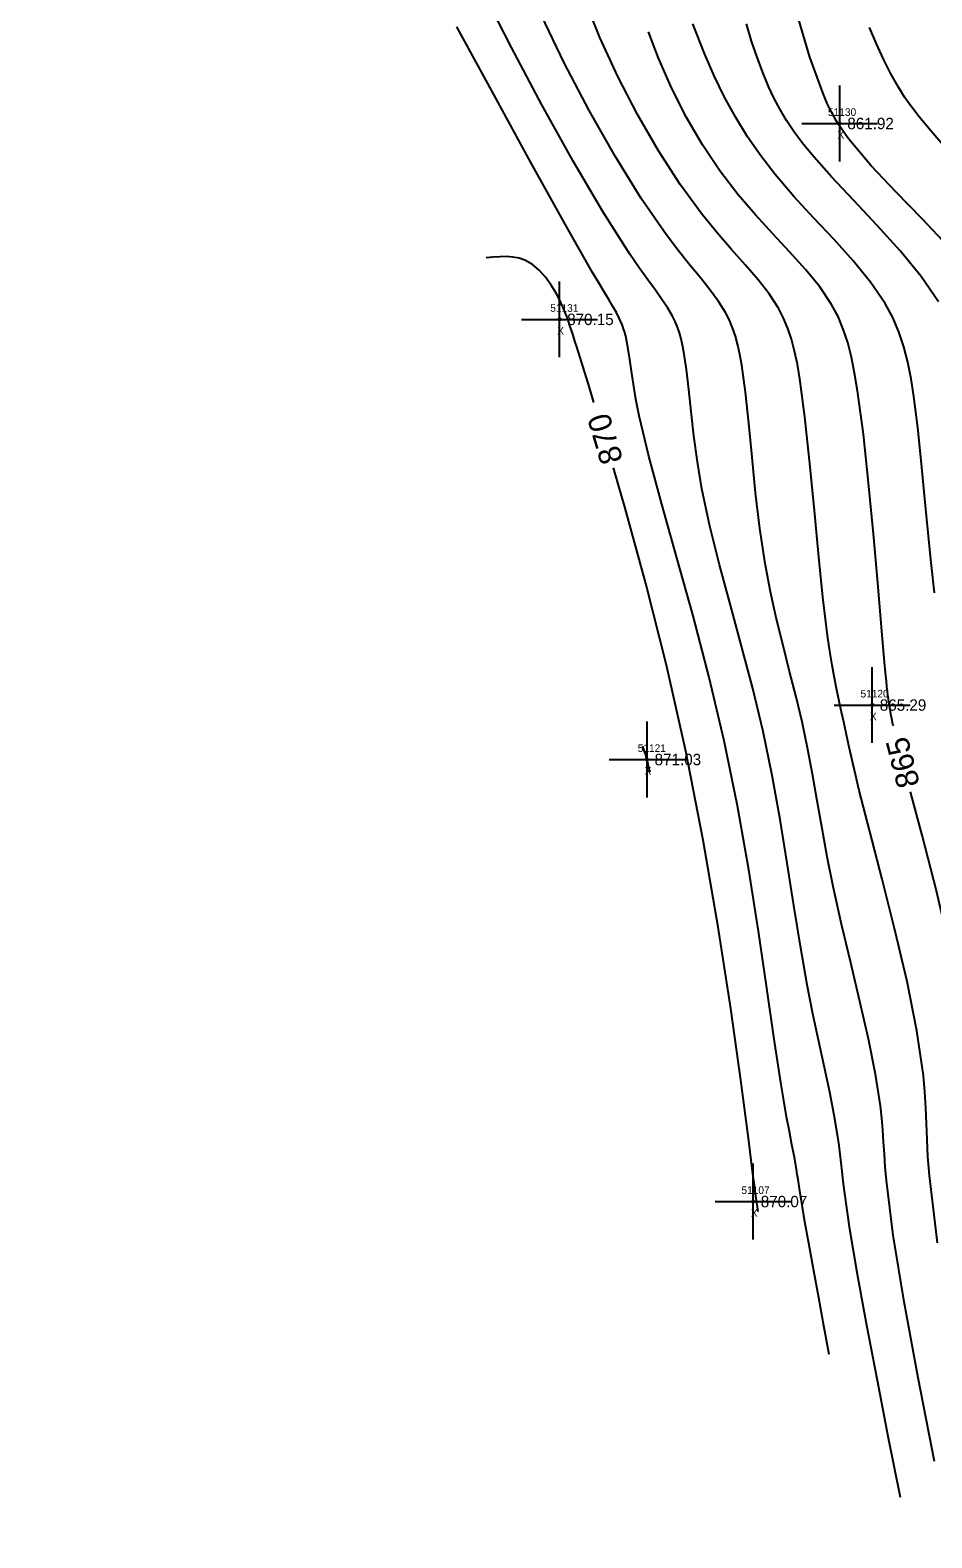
# Model space of a CAD drawing. Extents: x 1378535 to 1380697, y 997729 to 1000024.
# Drawn here: x 1380345.6 to 1380464.6, y 997856.9 to 998055.6 of the extents above; entities that cross this region are included whole.
import ezdxf

# ---------------------------------------------------------------- set-up
doc = ezdxf.new("R2010")
doc.units = 0
for name, color, linetype in [('RD_DTM_BkLn1', 7, 'Continuous'), ('RD_DTM_Major1', 7, 'Continuous'), ('RD_DTM_Major1_Lbl', 7, 'Continuous'), ('RD_DTM_Minor1', 7, 'Continuous'), ('RD_EX_Misc', 7, 'Continuous'), ('RD_EX_Misc_txCode', 7, 'Continuous'), ('RD_EX_Road', 7, 'Continuous'), ('RD_EX_TX_Misc_ELEV', 7, 'Continuous'), ('RD_SMD_Locator', 7, 'Continuous')]:
    doc.layers.add(name, color=color, linetype=linetype)

msp = doc.modelspace()

# ---------------------------------------------------------------- linework, layer by layer
at = {"layer": 'RD_DTM_BkLn1'}
msp.add_spline([(1380561.34, 997899.22), (1380543.7, 997960.78), (1380525.01, 998016.6), (1380501.32, 998075.31), (1380476.75, 998129.12), (1380448.82, 998181.2), (1380418.35, 998233.12), (1380383.22, 998285.15), (1380349.47, 998331.42), (1380310.82, 998378.03), (1380271.62, 998420.47), (1380231.53, 998459.85)], degree=3, dxfattribs=at)
at = {"layer": 'RD_DTM_Major1'}
for points in [[(1380459.47, 997963.94), (1380459.42, 997964.16), (1380459.28, 997964.83), (1380459.15, 997965.44), (1380459.08, 997965.86), (1380459, 997966.26), (1380458.94, 997966.66), (1380458.88, 997967.06), (1380458.82, 997967.47), (1380458.76, 997967.9), (1380458.69, 997968.48), (1380458.62, 997969.11), (1380458.55, 997969.79), (1380458.47, 997970.54), (1380458.39, 997971.37), (1380458.31, 997972.29), (1380457.91, 997976.94), (1380457.42, 997982.75), (1380456.85, 997989.24), (1380456.21, 997995.94), (1380455.51, 998002.38), (1380454.75, 998008.08), (1380454.36, 998010.42), (1380453.94, 998012.52), (1380453.45, 998014.43), (1380452.87, 998016.2), (1380452.17, 998017.85), (1380451.32, 998019.44), (1380449.75, 998021.76), (1380447.88, 998024.06), (1380445.79, 998026.39), (1380443.56, 998028.78), (1380441.27, 998031.27), (1380439.01, 998033.91), (1380436.59, 998037.08), (1380434.31, 998040.48), (1380432.19, 998044.08), (1380430.24, 998047.9), (1380428.48, 998051.91), (1380427.18, 998055.37)], [(1380419.98, 998006.55), (1380419.39, 998008.5), (1380417.72, 998013.86), (1380417.51, 998014.5), (1380417.32, 998015.1), (1380417.15, 998015.66), (1380416.98, 998016.17), (1380416.81, 998016.66), (1380416.65, 998017.12), (1380416.59, 998017.32), (1380416.52, 998017.51), (1380416.45, 998017.7), (1380416.38, 998017.88), (1380416.31, 998018.07), (1380416.24, 998018.25), (1380416.13, 998018.52), (1380416.02, 998018.78), (1380415.91, 998019.04), (1380415.79, 998019.3), (1380415.67, 998019.56), (1380415.55, 998019.83), (1380414.98, 998020.93), (1380414.33, 998022.02), (1380413.6, 998023.05), (1380412.77, 998023.97), (1380411.87, 998024.73), (1380410.88, 998025.29), (1380410.09, 998025.55), (1380409.27, 998025.7), (1380408.42, 998025.76), (1380407.54, 998025.74), (1380406.65, 998025.69), (1380405.75, 998025.61)], [(1380441.64, 997899.9), (1380441.54, 997900.54), (1380441.46, 997901.04), (1380441.37, 997901.64), (1380441.36, 997901.75), (1380441.34, 997901.86), (1380441.32, 997901.97), (1380441.28, 997902.27), (1380441.24, 997902.59), (1380441.2, 997902.93), (1380441.15, 997903.31), (1380441.09, 997903.72), (1380441.04, 997904.16), (1380440.35, 997909.56), (1380439.35, 997917.23), (1380438.02, 997926.67), (1380436.37, 997937.37), (1380434.39, 997948.84), (1380432.09, 997960.57), (1380429.53, 997971.91), (1380426.81, 997982.69), (1380424.11, 997992.59), (1380422.56, 997997.93)], [(1380478.43, 997856.9), (1380477.24, 997862.31), (1380475.33, 997871.26), (1380473.42, 997880.79), (1380471.7, 997890.27), (1380470.37, 997899.12), (1380469.61, 997906.72), (1380469.51, 997909.33), (1380469.48, 997911.74), (1380469.48, 997914.03), (1380469.47, 997916.3), (1380469.4, 997918.65), (1380469.22, 997921.17), (1380468.33, 997927.57), (1380466.89, 997934.75), (1380465.14, 997942.19), (1380463.3, 997949.35), (1380461.73, 997955.23)]]:
    msp.add_lwpolyline(points, dxfattribs=at)
at = {"layer": 'RD_DTM_Minor1'}
for points in [[(1380460.41, 997862.23), (1380458.85, 997870.03), (1380457.36, 997877.64), (1380455.97, 997884.89), (1380454.74, 997891.59), (1380453.74, 997897.56), (1380453.01, 997902.61), (1380452.85, 997903.92), (1380452.71, 997905.16), (1380452.58, 997906.34), (1380452.45, 997907.48), (1380452.31, 997908.62), (1380452.16, 997909.76), (1380451.68, 997912.61), (1380451.08, 997915.65), (1380450.38, 997918.88), (1380449.63, 997922.3), (1380448.85, 997925.94), (1380448.09, 997929.79), (1380447.2, 997934.88), (1380446.34, 997940.26), (1380445.47, 997945.84), (1380444.53, 997951.57), (1380443.48, 997957.37), (1380442.28, 997963.17), (1380440.93, 997968.83), (1380439.46, 997974.4), (1380437.97, 997979.84), (1380436.55, 997985.14), (1380435.27, 997990.25), (1380434.22, 997995.14), (1380433.62, 997998.73), (1380433.15, 998002.14), (1380432.79, 998005.33), (1380432.48, 998008.25), (1380432.18, 998010.88), (1380431.84, 998013.17), (1380431.67, 998014.08), (1380431.48, 998014.92), (1380431.25, 998015.71), (1380430.99, 998016.46), (1380430.69, 998017.19), (1380430.34, 998017.91), (1380429.71, 998018.99), (1380428.95, 998020.12), (1380428.08, 998021.34), (1380427.08, 998022.71), (1380425.95, 998024.28), (1380424.71, 998026.08), (1380421.2, 998031.61), (1380417.25, 998038.34), (1380413.12, 998045.76), (1380409.08, 998053.34), (1380405.41, 998060.57)], [(1380465.29, 997895.79), (1380464.22, 997904.67), (1380464.04, 997907.14), (1380463.93, 997909.4), (1380463.85, 997911.52), (1380463.76, 997913.58), (1380463.64, 997915.66), (1380463.44, 997917.85), (1380462.58, 997923.7), (1380461.27, 997930.22), (1380459.68, 997937.02), (1380457.99, 997943.73), (1380456.37, 997949.99), (1380454.98, 997955.41), (1380454.47, 997957.51), (1380454.03, 997959.4), (1380453.64, 997961.13), (1380453.29, 997962.73), (1380452.96, 997964.24), (1380452.65, 997965.71), (1380452.33, 997967.16), (1380452.02, 997968.64), (1380451.7, 997970.21), (1380451.38, 997971.91), (1380451.07, 997973.76), (1380450.77, 997975.83), (1380450.17, 997980.87), (1380449.59, 997986.64), (1380449.02, 997992.77), (1380448.43, 997998.89), (1380447.81, 998004.65), (1380447.13, 998009.67), (1380446.81, 998011.57), (1380446.45, 998013.3), (1380446.04, 998014.87), (1380445.56, 998016.31), (1380444.99, 998017.67), (1380444.31, 998018.97), (1380443.08, 998020.84), (1380441.62, 998022.72), (1380439.96, 998024.64), (1380438.14, 998026.68), (1380436.22, 998028.88), (1380434.24, 998031.31), (1380431.34, 998035.28), (1380428.47, 998039.71), (1380425.7, 998044.5), (1380423.11, 998049.51), (1380420.76, 998054.63), (1380418.72, 998059.75)], [(1380464.91, 997866.98), (1380462.74, 997877.98), (1380460.89, 997888.02), (1380459.46, 997896.8), (1380458.56, 997903.99), (1380458.4, 997905.79), (1380458.29, 997907.47), (1380458.18, 997909.07), (1380458.08, 997910.63), (1380457.95, 997912.2), (1380457.78, 997913.82), (1380457.12, 997918.03), (1380456.19, 997922.67), (1380455.07, 997927.6), (1380453.86, 997932.67), (1380452.65, 997937.77), (1380451.54, 997942.75), (1380450.76, 997946.64), (1380450.07, 997950.39), (1380449.42, 997954.02), (1380448.79, 997957.56), (1380448.14, 997961.02), (1380447.42, 997964.43), (1380446.63, 997967.76), (1380445.78, 997971.1), (1380444.92, 997974.49), (1380444.06, 997977.96), (1380443.26, 997981.56), (1380442.55, 997985.32), (1380441.86, 997989.93), (1380441.3, 997994.65), (1380440.83, 997999.33), (1380440.4, 998003.8), (1380439.96, 998007.9), (1380439.47, 998011.47), (1380439.23, 998012.85), (1380438.96, 998014.11), (1380438.64, 998015.28), (1380438.27, 998016.37), (1380437.84, 998017.4), (1380437.33, 998018.4), (1380436.41, 998019.86), (1380435.32, 998021.34), (1380434.06, 998022.91), (1380432.66, 998024.61), (1380431.12, 998026.52), (1380429.48, 998028.68), (1380426.21, 998033.44), (1380422.78, 998038.99), (1380419.33, 998045.04), (1380416.04, 998051.32), (1380413.06, 998057.52)], [(1380466.71, 998027.09), (1380463.26, 998030.73), (1380459.78, 998034.3), (1380456.54, 998037.74), (1380453.8, 998040.96), (1380453.47, 998041.41), (1380453.14, 998041.85), (1380452.83, 998042.29), (1380452.54, 998042.73), (1380452.25, 998043.17), (1380451.98, 998043.62), (1380451.66, 998044.18), (1380451.35, 998044.76), (1380451.05, 998045.35), (1380450.76, 998045.96), (1380450.47, 998046.59), (1380450.19, 998047.25), (1380448.47, 998052.04), (1380446.78, 998057.7)], [(1380451.02, 997881.07), (1380450.31, 997884.84), (1380449.62, 997888.54), (1380448.96, 997892.11), (1380448.35, 997895.47), (1380447.81, 997898.55), (1380447.35, 997901.3), (1380447.23, 997902.05), (1380446.91, 997904.13), (1380446.8, 997904.79), (1380446.69, 997905.45), (1380446.41, 997907.05), (1380446.1, 997908.71), (1380445.76, 997910.47), (1380445.39, 997912.4), (1380445.01, 997914.53), (1380444.61, 997916.91), (1380443.74, 997922.62), (1380442.78, 997929.34), (1380441.68, 997936.85), (1380440.4, 997944.94), (1380438.91, 997953.38), (1380437.15, 997961.95), (1380435.17, 997970.31), (1380433.05, 997978.41), (1380430.92, 997986.08), (1380428.93, 997993.15), (1380427.23, 997999.45), (1380425.95, 998004.79), (1380425.52, 998006.98), (1380425.19, 998008.93), (1380424.93, 998010.66), (1380424.72, 998012.2), (1380424.51, 998013.57), (1380424.28, 998014.79), (1380424.16, 998015.28), (1380424.03, 998015.76), (1380423.89, 998016.23), (1380423.72, 998016.69), (1380423.53, 998017.16), (1380423.31, 998017.64), (1380422.93, 998018.39), (1380422.47, 998019.2), (1380421.94, 998020.11), (1380421.32, 998021.14), (1380420.61, 998022.32), (1380419.8, 998023.68), (1380416.16, 998030.06), (1380411.67, 998038.17), (1380406.77, 998047.13), (1380401.89, 998056.06)], [(1380464.89, 997981.44), (1380464.44, 997985.45), (1380464.01, 997989.8), (1380463.59, 997994.33), (1380463.16, 997998.87), (1380462.69, 998003.26), (1380462.17, 998007.34), (1380461.81, 998009.66), (1380461.38, 998011.83), (1380460.86, 998013.88), (1380460.21, 998015.83), (1380459.39, 998017.73), (1380458.38, 998019.6), (1380456.47, 998022.39), (1380454.18, 998025.19), (1380451.65, 998028), (1380448.99, 998030.84), (1380446.36, 998033.7), (1380443.87, 998036.57), (1380441.97, 998039.03), (1380440.24, 998041.53), (1380438.67, 998044.1), (1380437.21, 998046.77), (1380435.85, 998049.58), (1380434.56, 998052.55), (1380433.02, 998056.46)], [(1380465.42, 998019.79), (1380463.13, 998023.13), (1380460.37, 998026.51), (1380457.34, 998029.87), (1380454.26, 998033.15), (1380451.31, 998036.28), (1380448.7, 998039.22), (1380447.45, 998040.77), (1380446.35, 998042.26), (1380445.38, 998043.71), (1380444.52, 998045.15), (1380443.74, 998046.6), (1380443.04, 998048.09), (1380442.24, 998050.01), (1380441.49, 998052.04), (1380440.78, 998054.18), (1380440.09, 998056.46)], [(1380466.22, 998040.23), (1380464.44, 998042.28), (1380462.83, 998044.23), (1380462.33, 998044.88), (1380461.85, 998045.51), (1380461.4, 998046.15), (1380460.96, 998046.78), (1380460.54, 998047.43), (1380460.14, 998048.09), (1380459.12, 998049.87), (1380458.15, 998051.78), (1380457.23, 998053.82), (1380456.34, 998055.98)], [(1380427.37, 997957.83), (1380427.19, 997958.6), (1380427.13, 997958.85), (1380427.07, 997959.1), (1380427.01, 997959.34), (1380426.94, 997959.59), (1380426.87, 997959.84), (1380426.8, 997960.08), (1380426.72, 997960.31), (1380426.65, 997960.54), (1380426.52, 997960.92), (1380426.42, 997961.22)]]:
    msp.add_lwpolyline(points, dxfattribs=at)
at = {"layer": 'RD_EX_Misc'}
for p, q in [((1380452.4, 998038.31), (1380452.4, 998048.31)), ((1380447.4, 998043.31), (1380457.4, 998043.31)), ((1380415.44, 998012.49), (1380415.44, 998022.49)), ((1380410.44, 998017.49), (1380420.44, 998017.49)), ((1380456.68, 997961.66), (1380456.68, 997971.66)), ((1380451.68, 997966.66), (1380461.68, 997966.66)), ((1380426.98, 997954.48), (1380426.98, 997964.48)), ((1380421.98, 997959.48), (1380431.98, 997959.48)), ((1380440.98, 997896.22), (1380440.98, 997906.22)), ((1380435.98, 997901.22), (1380445.98, 997901.22))]:
    msp.add_line(p, q, dxfattribs=at)
at = {"layer": 'RD_EX_Road'}
for points in [[(1380571.28, 997900.85), (1380553.84, 997963.23), (1380535.07, 998018.79), (1380510.81, 998079.18), (1380486.36, 998133.16), (1380458.39, 998185.94), (1380428.11, 998238.22), (1380392.69, 998291.14), (1380357.52, 998337.62), (1380319.37, 998385.16), (1380279.26, 998428.68), (1380239.6, 998468.13), (1380183.37, 998518.83)], [(1380551.89, 997897.33), (1380534.24, 997958.2), (1380514.83, 998013.47), (1380491.08, 998070.75), (1380467.52, 998124.4), (1380439.88, 998176.53), (1380409.17, 998228.12), (1380375.89, 998278.45), (1380340.75, 998326.22), (1380303.33, 998371.14), (1380263.98, 998413.97), (1380224.66, 998452.64), (1380168.71, 998504.79)]]:
    msp.add_spline(points, degree=3, dxfattribs=at)
at = {"layer": 'RD_SMD_Locator'}
for centre in [(1380452.4, 998043.31), (1380415.44, 998017.49), (1380456.68, 997966.66), (1380426.98, 997959.48), (1380440.98, 997901.22)]:
    msp.add_circle(centre, 0.15, dxfattribs=at)

# ---------------------------------------------------------------- texts
at = {"layer": 'RD_DTM_Major1_Lbl'}
for s, rotation, p in [('870', 106.6107, (1380423.84, 997998.94)), ('865', 104.5173, (1380462.99, 997956.2))]:
    msp.add_text(s, height=3, rotation=rotation, dxfattribs=at).set_placement(p)
at = {"layer": 'RD_EX_Misc_txCode'}
for s, p in [('51130', (1380450.85, 998044.31)), ('X', (1380452.09, 998041.31)), ('51131', (1380414.21, 998018.49)), ('X', (1380415.12, 998015.49)), ('51120', (1380455.13, 997967.66)), ('X', (1380456.37, 997964.66)), ('51121', (1380425.75, 997960.48)), ('X', (1380426.66, 997957.48)), ('51107', (1380439.43, 997902.22)), ('X', (1380440.67, 997899.22))]:
    msp.add_text(s, height=1, dxfattribs=at).set_placement(p)
at = {"layer": 'RD_EX_TX_Misc_ELEV'}
for s, p in [('861.92', (1380453.4, 998042.56)), ('870.15', (1380416.44, 998016.74)), ('865.29', (1380457.68, 997965.91)), ('871.03', (1380427.98, 997958.73)), ('870.07', (1380441.98, 997900.47))]:
    msp.add_text(s, height=1.5, dxfattribs=at).set_placement(p)

doc.saveas('drawing.dxf')
